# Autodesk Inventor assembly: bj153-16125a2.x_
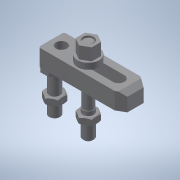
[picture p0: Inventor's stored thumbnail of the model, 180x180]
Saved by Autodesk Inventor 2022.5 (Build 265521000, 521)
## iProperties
Part Number: bj153-16125a2.x_
Material: 一般
Document SubType Name: Assembly
Designer: ImaoCorp
Sending System: SOLIDWORKS 2017-2017317
MC: AMD64
MC_MODEL: Intel64 Family 6 Model 60 Stepping 3, GenuineIntel
OS: Windows_NT
FRU: Parasolid Version 29.0, build 201,  4-17-2017
FORMAT: text
GUISE: transmit
KEY: bj153-16125a2
FILE: bj153-16125a2.x_t
DATE: Fri Mar 15 10:23:19 2019
Author: ImaoCorp
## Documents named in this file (7)
- X:\14_SW2022-Inv2022\00_全2023-1023新製品(TCC)まで\b\bj153-16125a2\BJ153-16125A2.iam
- X:\14_SW2022-Inv2022\00_全2023-1023新製品(TCC)まで\b\bj153-16125a2\bj153-16125a2_01.ipt
- X:\14_SW2022-Inv2022\00_全2023-1023新製品(TCC)まで\b\bj153-16125a2\bj153-16125a2_02.ipt
- X:\14_SW2022-Inv2022\00_全2023-1023新製品(TCC)まで\b\bj153-16125a2\bj153-16125a2_03.ipt
- X:\14_SW2022-Inv2022\00_全2023-1023新製品(TCC)まで\b\bj153-16125a2\bj153-16125a2_04.ipt
- X:\14_SW2022-Inv2022\00_全2023-1023新製品(TCC)まで\b\bj153-16125a2\bj153-16125a2_05.ipt
- X:\14_SW2022-Inv2022\00_全2023-1023新製品(TCC)まで\b\bj153-16125a2\bj153-16125a2_06.ipt
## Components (6 placed, 6 different names)
1. bj153-16125a2_01
2. bj153-16125a2_02
3. bj153-16125a2_03
4. bj153-16125a2_04
5. bj153-16125a2_05
6. bj153-16125a2_06
